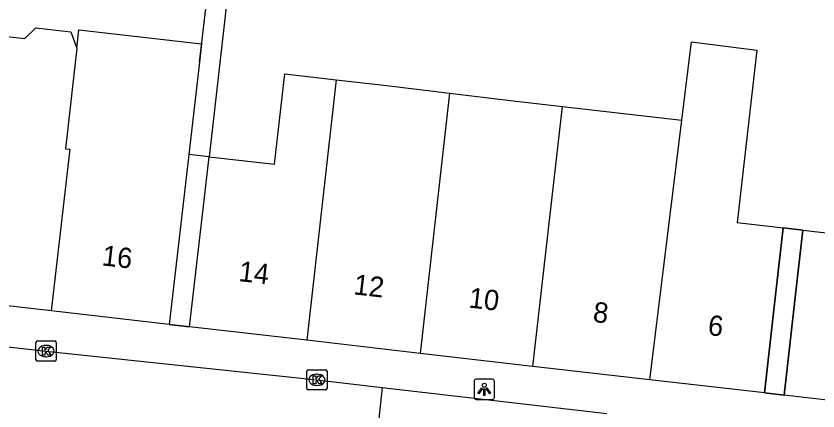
# Model space of a CAD drawing. Extents: x 161696 to 162377, y 380761 to 381673.
# Drawn here: x 162202.16 to 162241.77, y 381135.22 to 381154.7 of the extents above; entities that cross this region are included whole.
import ezdxf

# ---------------------------------------------------------------- set-up
doc = ezdxf.new("R2010")
doc.units = 0
for name, color, linetype in [('IMGEO_Erf', 7, 'Continuous'), ('IMGEO_Kolk', 7, 'Continuous'), ('IMGEO_Lichtpunt', 7, 'Continuous'), ('IMGEO_Pand', 7, 'Continuous'), ('IMGEO_Pand_nummerreeks', 7, 'Continuous'), ('IMGEO_Pand_overbouw', 7, 'Continuous'), ('IMGEO_Rijbaan_lokaal_open', 7, 'Continuous'), ('IMGEO_Voetpad_open', 7, 'Continuous')]:
    doc.layers.add(name, color=color, linetype=linetype)

msp = doc.modelspace()

# ---------------------------------------------------------------- linework, layer by layer
at = {"layer": 'IMGEO_Erf'}
msp.add_lwpolyline([(162240.055, 381144.252), (162241.026, 381144.141)], dxfattribs=at)
at = {"layer": 'IMGEO_Kolk'}
for p, q in [((162203.145, 381137.742), (162203.145, 381138.594)), ((162203.22, 381138.668), (162204.072, 381138.668)), ((162203.633, 381138.448), (162203.658, 381138.448)), ((162204.146, 381138.594), (162204.146, 381137.742)), ((162204.072, 381137.668), (162203.22, 381137.668)), ((162203.656, 381137.888), (162203.631, 381137.888)), ((162216.521, 381136.325), (162216.521, 381137.177)), ((162216.596, 381137.251), (162217.448, 381137.251)), ((162217.522, 381137.177), (162217.522, 381136.325)), ((162217.009, 381137.031), (162217.034, 381137.031)), ((162217.032, 381136.471), (162217.007, 381136.471)), ((162217.448, 381136.251), (162216.596, 381136.251))]:
    msp.add_line(p, q, dxfattribs=at)
for points in [[(162203.145, 381137.742), (162203.145, 381138.594)], [(162203.22, 381138.668), (162204.072, 381138.668)], [(162203.466, 381138.368), (162203.589, 381138.368), (162203.589, 381138.217), (162203.719, 381138.368), (162203.883, 381138.368), (162203.737, 381138.217), (162203.89, 381137.968), (162203.738, 381137.968), (162203.653, 381138.132), (162203.589, 381138.065), (162203.589, 381137.968), (162203.466, 381137.968), (162203.466, 381138.368)], [(162204.146, 381138.594), (162204.146, 381137.742)], [(162204.072, 381137.668), (162203.22, 381137.668)], [(162216.521, 381136.325), (162216.521, 381137.177)], [(162216.596, 381137.251), (162217.448, 381137.251)], [(162217.522, 381137.177), (162217.522, 381136.325)], [(162216.842, 381136.951), (162216.965, 381136.951), (162216.965, 381136.8), (162217.095, 381136.951), (162217.259, 381136.951), (162217.113, 381136.8), (162217.266, 381136.551), (162217.114, 381136.551), (162217.029, 381136.715), (162216.965, 381136.648), (162216.965, 381136.551), (162216.842, 381136.551), (162216.842, 381136.951)], [(162217.448, 381136.251), (162216.596, 381136.251)]]:
    msp.add_lwpolyline(points, dxfattribs=at)
for centre, start, end in [((162203.222, 381138.592), 91.552, 178.448), ((162203.222, 381138.592), 91.552, 178.448), ((162204.07, 381138.592), 1.552, 88.448), ((162204.07, 381138.592), 1.552, 88.448), ((162203.222, 381137.744), 181.552, 268.448), ((162203.222, 381137.744), 181.552, 268.448), ((162204.07, 381137.744), 271.552, 358.448), ((162204.07, 381137.744), 271.552, 358.448), ((162216.598, 381137.175), 91.552, 178.448), ((162216.598, 381137.175), 91.552, 178.448), ((162217.446, 381137.175), 1.552, 88.448), ((162217.446, 381137.175), 1.552, 88.448), ((162216.598, 381136.327), 181.552, 268.448), ((162216.598, 381136.327), 181.552, 268.448), ((162217.446, 381136.327), 271.552, 358.448), ((162217.446, 381136.327), 271.552, 358.448)]:
    msp.add_arc(centre, 0.0765, start, end, dxfattribs=at)
for centre, major_axis, ratio, start_param, end_param in [((162203.632, 381138.168), (-0.387, 0.002), 0.722429, 4.712389, 7.853982), ((162203.657, 381138.168), (-0.39, 0.002), 0.717154, 1.570796, 4.712389), ((162217.008, 381136.751), (-0.387, 0.002), 0.722429, 4.712389, 7.853982), ((162217.033, 381136.751), (-0.39, 0.002), 0.717154, 1.570796, 4.712389)]:
    msp.add_ellipse(centre, major_axis=major_axis, ratio=ratio, start_param=start_param, end_param=end_param, dxfattribs=at)
at = {"layer": 'IMGEO_Lichtpunt'}
for p, q in [((162225.69, 381136.783), (162224.882, 381136.783)), ((162225.69, 381136.783), (162224.882, 381136.783)), ((162224.788, 381136.688), (162224.788, 381135.881)), ((162224.788, 381136.688), (162224.788, 381135.881)), ((162225.784, 381135.881), (162225.784, 381136.688)), ((162225.784, 381135.881), (162225.784, 381136.688)), ((162224.882, 381135.787), (162225.69, 381135.787)), ((162224.882, 381135.787), (162225.69, 381135.787))]:
    msp.add_line(p, q, dxfattribs=at)
for points in [[(162225.162, 381136.352), (162225.201, 381136.324), (162225.013, 381136.062), (162224.975, 381136.089), (162225.162, 381136.352)], [(162225.264, 381136.304), (162225.311, 381136.304), (162225.311, 381135.982), (162225.264, 381135.982), (162225.264, 381136.304)], [(162225.374, 381136.324), (162225.412, 381136.351), (162225.599, 381136.089), (162225.56, 381136.061), (162225.374, 381136.324)]]:
    msp.add_lwpolyline(points, dxfattribs=at)
msp.add_circle((162225.287, 381136.486), 0.0994, dxfattribs=at)
for centre, start, end in [((162224.882, 381136.688), 90, 180), ((162224.882, 381136.688), 90, 180), ((162225.69, 381136.688), 0, 90), ((162225.69, 381136.688), 0, 90), ((162224.882, 381135.881), 180, 270), ((162224.882, 381135.881), 180, 270), ((162225.69, 381135.881), 270, 0), ((162225.69, 381135.881), 270, 360)]:
    msp.add_arc(centre, 0.0946, start, end, dxfattribs=at)
at = {"layer": 'IMGEO_Pand'}
for points in [[(162199.62, 381153.925), (162202.606, 381153.582), (162203.142, 381154.11), (162204.868, 381153.912), (162204.933, 381153.739), (162205.168, 381153.112)], [(162205.168, 381153.112), (162205.271, 381154.022), (162211.32, 381153.326), (162211.216, 381152.421)], [(162235.042, 381149.552), (162235.519, 381153.417), (162238.749, 381153.018), (162237.773, 381144.514), (162240.055, 381144.252)], [(162205.168, 381153.112), (162205.053, 381152.097), (162204.604, 381148.149), (162204.812, 381148.125), (162203.896, 381140.149)], [(162241.026, 381144.141), (162243.34, 381143.875), (162243.696, 381146.971), (162243.9, 381148.743), (162242.923, 381148.855), (162243.279, 381151.954), (162243.362, 381152.677), (162247.721, 381152.177), (162247.637, 381151.455), (162247.361, 381149.074)], [(162211.216, 381152.421), (162210.695, 381147.869), (162210.303, 381144.447), (162209.732, 381139.479)], [(162211.694, 381147.755), (162214.92, 381147.384), (162215.433, 381151.849), (162217.978, 381151.557)], [(162217.978, 381151.557), (162216.517, 381138.7)], [(162217.978, 381151.557), (162220.481, 381151.27), (162223.577, 381150.891)], [(162223.577, 381150.891), (162222.118, 381138.057)], [(162223.577, 381150.891), (162226.577, 381150.523), (162229.147, 381150.228)], [(162227.691, 381137.417), (162229.147, 381150.228)], [(162229.147, 381150.228), (162231.736, 381149.931), (162235.042, 381149.552)], [(162233.461, 381136.755), (162235.042, 381149.552)], [(162210.731, 381139.364), (162211.302, 381144.332), (162211.694, 381147.755)], [(162239.12, 381136.105), (162239.691, 381141.073), (162240.055, 381144.252)], [(162241.026, 381144.141), (162240.662, 381140.962), (162240.091, 381135.994)], [(162203.896, 381140.149), (162198.134, 381140.811)], [(162209.732, 381139.479), (162203.896, 381140.149)], [(162216.517, 381138.7), (162210.731, 381139.364)], [(162222.118, 381138.057), (162216.517, 381138.7)], [(162227.691, 381137.417), (162222.118, 381138.057)], [(162233.461, 381136.755), (162227.691, 381137.417)], [(162239.12, 381136.105), (162233.461, 381136.755)], [(162245.78, 381135.341), (162240.091, 381135.994)]]:
    msp.add_lwpolyline(points, dxfattribs=at)
at = {"layer": 'IMGEO_Pand_overbouw'}
for points in [[(162210.731, 381139.364), (162211.302, 381144.332), (162211.694, 381147.755), (162210.695, 381147.869), (162210.303, 381144.447), (162209.732, 381139.479)], [(162241.026, 381144.141), (162240.055, 381144.252), (162239.691, 381141.073), (162239.12, 381136.105), (162240.091, 381135.994), (162240.662, 381140.962)]]:
    msp.add_lwpolyline(points, close=True, dxfattribs=at)
at = {"layer": 'IMGEO_Rijbaan_lokaal_open'}
for points in [[(162186.489, 381140.14), (162200.716, 381138.494), (162203.646, 381138.166), (162217.018, 381136.75), (162220.241, 381136.371)], [(162220.241, 381136.371), (162219.754, 381131.77)], [(162220.241, 381136.371), (162231.336, 381135.092)]]:
    msp.add_lwpolyline(points, dxfattribs=at)
at = {"layer": 'IMGEO_Voetpad_open'}
for points in [[(162211.216, 381152.421), (162214.017, 381176.099), (162207.651, 381176.848), (162207.751, 381177.797)], [(162214.38, 381171.391), (162214.313, 381170.8), (162211.694, 381147.755)], [(162210.731, 381139.364), (162209.732, 381139.479)], [(162240.091, 381135.994), (162239.12, 381136.105)]]:
    msp.add_lwpolyline(points, dxfattribs=at)

# ---------------------------------------------------------------- texts
at = {"layer": 'IMGEO_Pand_nummerreeks'}
for s, rotation, p in [('16', 353.4396, (162206.371, 381142.402)), ('14', 353.4512, (162213.127, 381141.626)), ('12', 353.4512, (162218.801, 381140.974)), ('10', 353.4512, (162224.485, 381140.322)), ('8', 353.4512, (162230.621, 381139.617)), ('6', 353.4512, (162236.295, 381138.966))]:
    msp.add_text(s, height=1, rotation=rotation, dxfattribs=at).set_placement(p)

doc.saveas('drawing.dxf')
